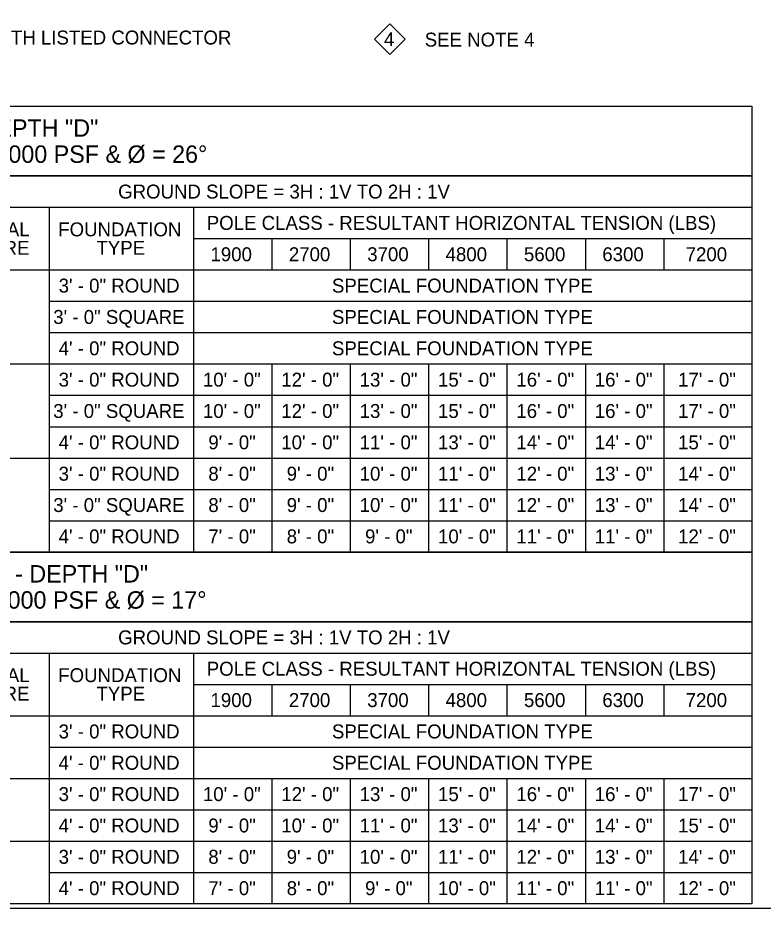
# Model space of a CAD drawing. Extents: x 99862 to 103151, y 100000 to 102076.
# Drawn here: x 101145 to 102001, y 100000 to 101022 of the extents above; entities that cross this region are included whole.
import ezdxf

# ---------------------------------------------------------------- set-up
doc = ezdxf.new("R2010")
doc.units = 0
for name, color, linetype in [('Level 1', 7, 'Continuous'), ('Level 20', 7, 'Continuous'), ('Level 40', 7, 'Continuous')]:
    doc.layers.add(name, color=color, linetype=linetype)

msp = doc.modelspace()

# ---------------------------------------------------------------- linework, layer by layer
at = {"layer": 'Level 1'}
msp.add_lwpolyline([(99862, 99999.5), (103151, 99999.5), (103151, 102075.5), (99862, 102075.5)], close=True, dxfattribs=at)
at = {"layer": 'Level 20'}
msp.add_lwpolyline([(101572.1, 101015.1), (101589.7, 100997.5), (101572.1, 100979.9), (101554.6, 100997.5)], close=True, dxfattribs=at)
at = {"layer": 'Level 40'}
for p, q in [((99867, 100804.5), (101987.9, 100804.5)), ((101180.9, 100804.5), (101180.9, 100408.5)), ((101346.7, 100804.5), (101346.7, 100408.5)), ((101346.7, 100768.5), (101987.9, 100768.5)), ((101436.7, 100768.5), (101436.7, 100732.5)), ((101526.7, 100768.5), (101526.7, 100732.5)), ((101616.7, 100768.5), (101616.7, 100732.5)), ((101706.7, 100768.5), (101706.7, 100732.5)), ((101796.7, 100768.5), (101796.7, 100732.5)), ((101886.7, 100768.5), (101886.7, 100732.5)), ((99867, 100732.5), (101987.9, 100732.5)), ((101180.9, 100696.5), (101987.9, 100696.5)), ((101180.9, 100660.5), (101987.9, 100660.5)), ((99867, 100624.5), (101987.9, 100624.5)), ((101436.7, 100624.5), (101436.7, 100408.5)), ((101526.7, 100624.5), (101526.7, 100408.5)), ((101616.7, 100624.5), (101616.7, 100408.5)), ((101706.7, 100624.5), (101706.7, 100408.5)), ((101796.7, 100624.5), (101796.7, 100408.5)), ((101886.7, 100624.5), (101886.7, 100408.5)), ((101180.9, 100588.5), (101987.9, 100588.5)), ((101180.9, 100552.5), (101987.9, 100552.5)), ((99867, 100516.5), (101987.9, 100516.5)), ((101180.9, 100480.5), (101987.9, 100480.5)), ((101180.9, 100444.5), (101987.9, 100444.5)), ((99867, 100292.5), (101987.9, 100292.5)), ((101180.9, 100292.5), (101180.9, 100004.5)), ((101346.7, 100292.5), (101346.7, 100004.5)), ((101346.7, 100256.5), (101987.9, 100256.5)), ((101436.7, 100256.5), (101436.7, 100220.5)), ((101526.7, 100256.5), (101526.7, 100220.5)), ((101616.7, 100256.5), (101616.7, 100220.5)), ((101706.7, 100256.5), (101706.7, 100220.5)), ((101796.7, 100256.5), (101796.7, 100220.5)), ((101886.7, 100256.5), (101886.7, 100220.5)), ((99867, 100220.5), (101987.9, 100220.5)), ((101180.9, 100184.5), (101987.9, 100184.5)), ((99867, 100148.5), (101987.9, 100148.5)), ((101436.7, 100148.5), (101436.7, 100004.5)), ((101526.7, 100148.5), (101526.7, 100004.5)), ((101616.7, 100148.5), (101616.7, 100004.5)), ((101706.7, 100148.5), (101706.7, 100004.5)), ((101796.7, 100148.5), (101796.7, 100004.5)), ((101886.7, 100148.5), (101886.7, 100004.5)), ((101180.9, 100112.5), (101987.9, 100112.5)), ((99867, 100076.5), (101987.9, 100076.5)), ((101180.9, 100040.5), (101987.9, 100040.5))]:
    msp.add_line(p, q, dxfattribs=at)
for points in [[(99867, 100920.5), (101987.9, 100920.5), (101987.9, 100840.5), (99867, 100840.5)], [(99867, 100840.5), (101987.9, 100840.5), (101987.9, 100408.5), (99867, 100408.5)], [(99867, 100408.5), (101987.9, 100408.5), (101987.9, 100328.5), (99867, 100328.5)], [(99867, 100328.5), (101987.9, 100328.5), (101987.9, 100004.5), (99867, 100004.5)]]:
    msp.add_lwpolyline(points, close=True, dxfattribs=at)

# ---------------------------------------------------------------- texts
at = {"layer": 'Level 20'}
for s, height, p in [('CLAMP CONDUCTOR TO STEEL REINFORCING WITH LISTED CONNECTOR ', 16, (100621.1, 100991.4)), ('4', 16, (101565.5, 100989.5)), ('SEE NOTE 4', 16, (101612.2, 100989)), ('ALTERNATE # 1 DRILLED SHAFT-TYPE CONSTRUCTION - DEPTH "D"', 20, (100358, 100885.5)), ('FOR LATERAL BEARING PRESSURE = 2500 PSF & Ø = 34°, 1500 PSF & Ø = 28°, 1000 PSF & Ø = 26°', 20, (100107.1, 100855.5)), ('GROUND SLOPE = 3H : 1V TO 2H : 1V', 16, (101260.1, 100814.5)), ('POLE CLASS - RESULTANT HORIZONTAL TENSION (LBS)', 16, (101361.9, 100778.5)), ('ALLOWABLE LATERAL', 16, (100927.8, 100771.1)), ('FOUNDATION', 16, (101191.3, 100771.1)), ('BEARING PRESSURE', 16, (100938.3, 100749.9)), ('TYPE', 16, (101235.2, 100749.9)), ('1900', 16, (101366.2, 100742.5)), ('2700', 16, (101456.2, 100742.5)), ('3700', 16, (101546.2, 100742.5)), ('4800', 16, (101636.2, 100742.5)), ('5600', 16, (101726.2, 100742.5)), ('6300', 16, (101816.2, 100742.5)), ('7200', 16, (101911.9, 100742.5)), ('3\' - 0" ROUND', 16, (101191.8, 100706.5)), ('SPECIAL FOUNDATION TYPE', 16, (101505.7, 100706.5)), ('3\' - 0" SQUARE', 16, (101185.6, 100670.5)), ('SPECIAL FOUNDATION TYPE', 16, (101505.7, 100670.5)), ('4\' - 0" ROUND', 16, (101191.8, 100634.5)), ('SPECIAL FOUNDATION TYPE', 16, (101505.7, 100634.5)), ('3\' - 0" ROUND', 16, (101191.8, 100598.5)), ('10\' - 0"', 16, (101357.5, 100598.5)), ('12\' - 0"', 16, (101447.5, 100598.5)), ('13\' - 0"', 16, (101537.5, 100598.5)), ('15\' - 0"', 16, (101627.5, 100598.5)), ('16\' - 0"', 16, (101717.5, 100598.5)), ('16\' - 0"', 16, (101807.5, 100598.5)), ('17\' - 0"', 16, (101903.2, 100598.5)), ('3\' - 0" SQUARE', 16, (101185.6, 100562.5)), ('10\' - 0"', 16, (101357.5, 100562.5)), ('12\' - 0"', 16, (101447.5, 100562.5)), ('13\' - 0"', 16, (101537.5, 100562.5)), ('15\' - 0"', 16, (101627.5, 100562.5)), ('16\' - 0"', 16, (101717.5, 100562.5)), ('16\' - 0"', 16, (101807.5, 100562.5)), ('17\' - 0"', 16, (101903.2, 100562.5)), ('4\' - 0" ROUND', 16, (101191.8, 100526.5)), ('9\' - 0"', 16, (101363.7, 100526.5)), ('10\' - 0"', 16, (101447.5, 100526.5)), ('11\' - 0"', 16, (101537.5, 100526.5)), ('13\' - 0"', 16, (101627.5, 100526.5)), ('14\' - 0"', 16, (101717.5, 100526.5)), ('14\' - 0"', 16, (101807.5, 100526.5)), ('15\' - 0"', 16, (101903.2, 100526.5)), ('3\' - 0" ROUND', 16, (101191.8, 100490.5)), ('8\' - 0"', 16, (101363.7, 100490.5)), ('9\' - 0"', 16, (101453.7, 100490.5)), ('10\' - 0"', 16, (101537.5, 100490.5)), ('11\' - 0"', 16, (101627.5, 100490.5)), ('12\' - 0"', 16, (101717.5, 100490.5)), ('13\' - 0"', 16, (101807.5, 100490.5)), ('14\' - 0"', 16, (101903.2, 100490.5)), ('3\' - 0" SQUARE', 16, (101185.6, 100454.5)), ('8\' - 0"', 16, (101363.7, 100454.5)), ('9\' - 0"', 16, (101453.7, 100454.5)), ('10\' - 0"', 16, (101537.5, 100454.5)), ('11\' - 0"', 16, (101627.5, 100454.5)), ('12\' - 0"', 16, (101717.5, 100454.5)), ('13\' - 0"', 16, (101807.5, 100454.5)), ('14\' - 0"', 16, (101903.2, 100454.5)), ('4\' - 0" ROUND', 16, (101191.8, 100418.5)), ('7\' - 0"', 16, (101363.7, 100418.5)), ('8\' - 0"', 16, (101453.7, 100418.5)), ('9\' - 0"', 16, (101543.7, 100418.5)), ('10\' - 0"', 16, (101627.5, 100418.5)), ('11\' - 0"', 16, (101717.5, 100418.5)), ('11\' - 0"', 16, (101807.5, 100418.5)), ('12\' - 0"', 16, (101903.2, 100418.5)), ('ALTERNATE # 2 CORRUGATED METAL PIPE TYPE CONSTRUCTION - DEPTH "D"', 20, (100269.5, 100373.5)), ('FOR LATERAL BEARING PRESSURE = 2500 PSF & Ø = 23°, 1500 PSF & Ø = 18°, 1000 PSF & Ø = 17°', 20, (100106.2, 100343.5)), ('GROUND SLOPE = 3H : 1V TO 2H : 1V', 16, (101260.1, 100302.5)), ('POLE CLASS - RESULTANT HORIZONTAL TENSION (LBS)', 16, (101361.9, 100266.5)), ('ALLOWABLE LATERAL', 16, (100927.8, 100259.1)), ('FOUNDATION', 16, (101191.3, 100259.1)), ('BEARING PRESSURE', 16, (100938.3, 100237.9)), ('TYPE', 16, (101235.2, 100237.9)), ('1900', 16, (101366.2, 100230.5)), ('2700', 16, (101456.2, 100230.5)), ('3700', 16, (101546.2, 100230.5)), ('4800', 16, (101636.2, 100230.5)), ('5600', 16, (101726.2, 100230.5)), ('6300', 16, (101816.2, 100230.5)), ('7200', 16, (101911.9, 100230.5)), ('3\' - 0" ROUND', 16, (101191.8, 100194.5)), ('SPECIAL FOUNDATION TYPE', 16, (101505.7, 100194.5)), ('4\' - 0" ROUND', 16, (101191.8, 100158.5)), ('SPECIAL FOUNDATION TYPE', 16, (101505.7, 100158.5)), ('3\' - 0" ROUND', 16, (101191.8, 100122.5)), ('10\' - 0"', 16, (101357.5, 100122.5)), ('12\' - 0"', 16, (101447.5, 100122.5)), ('13\' - 0"', 16, (101537.5, 100122.5)), ('15\' - 0"', 16, (101627.5, 100122.5)), ('16\' - 0"', 16, (101717.5, 100122.5)), ('16\' - 0"', 16, (101807.5, 100122.5)), ('17\' - 0"', 16, (101903.2, 100122.5)), ('4\' - 0" ROUND', 16, (101191.8, 100086.5)), ('9\' - 0"', 16, (101363.7, 100086.5)), ('10\' - 0"', 16, (101447.5, 100086.5)), ('11\' - 0"', 16, (101537.5, 100086.5)), ('13\' - 0"', 16, (101627.5, 100086.5)), ('14\' - 0"', 16, (101717.5, 100086.5)), ('14\' - 0"', 16, (101807.5, 100086.5)), ('15\' - 0"', 16, (101903.2, 100086.5)), ('3\' - 0" ROUND', 16, (101191.8, 100050.5)), ('8\' - 0"', 16, (101363.7, 100050.5)), ('9\' - 0"', 16, (101453.7, 100050.5)), ('10\' - 0"', 16, (101537.5, 100050.5)), ('11\' - 0"', 16, (101627.5, 100050.5)), ('12\' - 0"', 16, (101717.5, 100050.5)), ('13\' - 0"', 16, (101807.5, 100050.5)), ('14\' - 0"', 16, (101903.2, 100050.5)), ('4\' - 0" ROUND', 16, (101191.8, 100014.5)), ('7\' - 0"', 16, (101363.7, 100014.5)), ('8\' - 0"', 16, (101453.7, 100014.5)), ('9\' - 0"', 16, (101543.7, 100014.5)), ('10\' - 0"', 16, (101627.5, 100014.5)), ('11\' - 0"', 16, (101717.5, 100014.5)), ('11\' - 0"', 16, (101807.5, 100014.5)), ('12\' - 0"', 16, (101903.2, 100014.5))]:
    msp.add_text(s, height=height, dxfattribs=at).set_placement(p)

doc.saveas('drawing.dxf')
